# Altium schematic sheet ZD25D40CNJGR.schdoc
size 127 x 101 mm
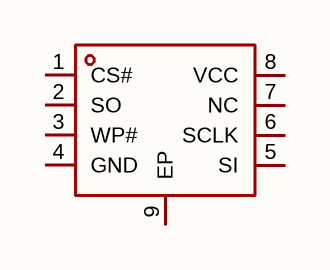
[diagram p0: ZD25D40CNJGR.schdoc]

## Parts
U?  zd25d40cnjgr  [USON-8_L1.5-W1.5-P0.40-BL-EP]  (value not drawn)

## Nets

Not connected (* = marked no-connect by the designer): U? 1(CS#) 2(SO) 3(WP#) 4(GND) 5(SI) 6(SCLK) 7(NC) 8(VCC) 9(EP)

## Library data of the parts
U? = zd25d40cnjgr: 接口类型:SPI;存储容量:4Mbit;时钟频率(fc):104MHz;; Manufacturer: Zetta(澜智); AddInBom: yes; ModelId: 5757cbfba7d0405e801eee9fb676df23; ModelName: USON-8_L1.5-W1.5-H0.5-P0.40-BL-EP; ModelTransform: 59.055,59.8424,0,180,0,0,0,0,0; Interface: SPI; Memory Size: 4Mbit; Clock Frequency: 104MHz; Voltage - Supply: 2.7V~3.6V; Standby Supply Current: 8uA; Program / Erase Cycles: 100000次; Page Programming Time (Tpp): 1.1ms; Block Erase Time(tBE): 2.6ms; Data Retention - TDR (Year): 20年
